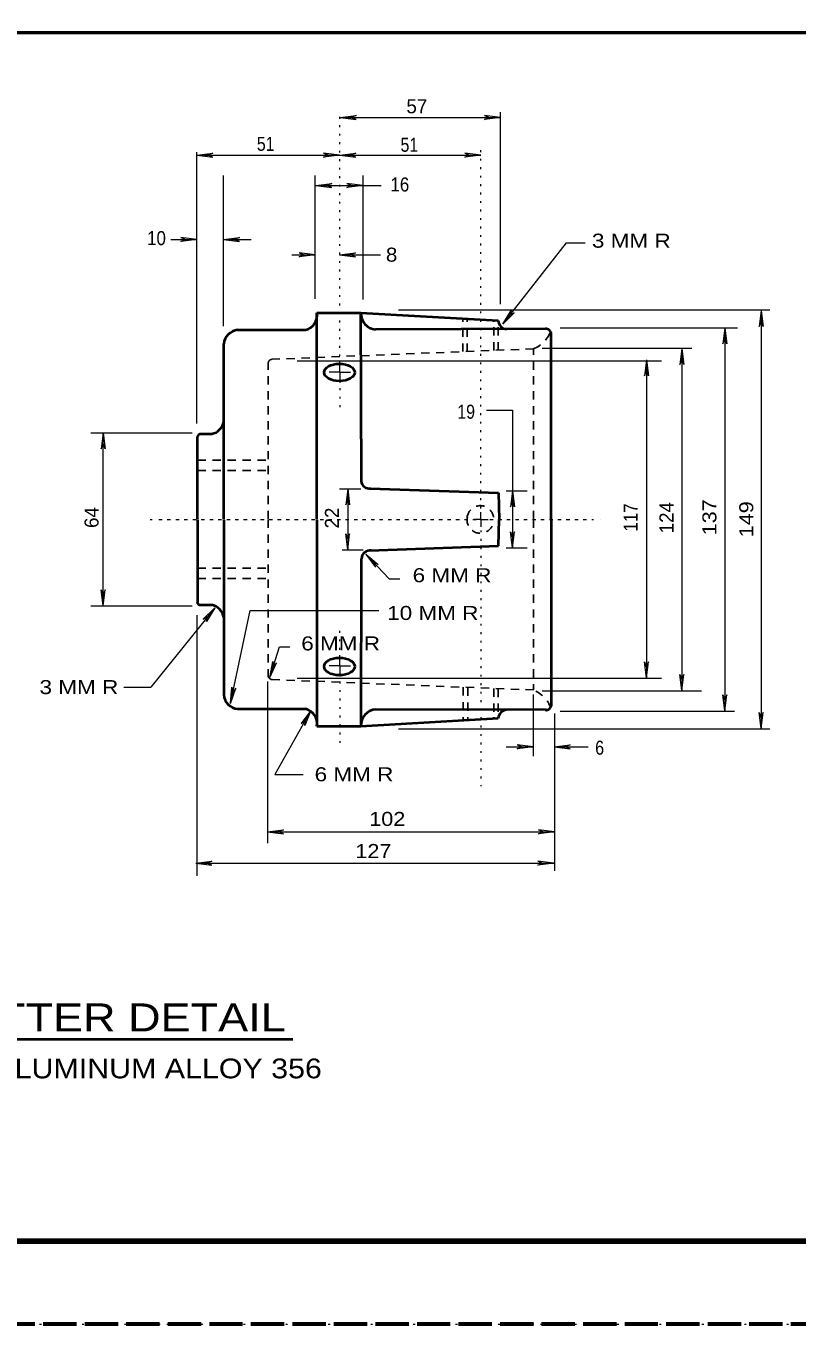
# Model space of a CAD drawing. Extents: x 312583 to 312854, y 144419 to 144597.
# Drawn here: x 312752.3 to 312794, y 144418.6 to 144488.9 of the extents above; entities that cross this region are included whole.
import ezdxf
from ezdxf.enums import TextEntityAlignment as Align

# ---------------------------------------------------------------- set-up
doc = ezdxf.new("R2010")
doc.units = 0
doc.header["$LTSCALE"] = 0.3
for name, pattern in [('DOTTED', [1.5, 0.3, -1.2]), ('LONG_DASHED', [7.5, 6, -1.5]), ('SHORT_DASHED', [2.7, 1.5, -1.2])]:
    doc.linetypes.add(name, pattern=pattern)
for name, color, linetype, lineweight in [('1', 7, 'Continuous', 40), ('2', 7, 'Continuous', 13), ('62', 7, 'DOTTED', 13), ('63', 7, 'LONG_DASHED', 60)]:
    doc.layers.add(name, color=color, linetype=linetype, lineweight=lineweight)

msp = doc.modelspace()

# ---------------------------------------------------------------- linework, layer by layer
at = {"layer": '1', "linetype": 'DOTTED', "lineweight": 13}
for p, q in [((312769.2617, 144471.0383), (312769.2617, 144484.2326)), ((312776.9054, 144462.7889), (312776.9054, 144482.3849)), ((312769.2617, 144469.3056), (312769.2617, 144467.9869)), ((312758.996, 144462.1986), (312783.376, 144462.1986)), ((312759.5404, 144462.1986), (312782.6247, 144462.1986)), ((312776.9054, 144461.6006), (312776.9054, 144447.7316)), ((312769.2617, 144455.1299), (312769.2617, 144456.3949)), ((312769.2617, 144453.4049), (312769.2617, 144449.9473))]:
    msp.add_line(p, q, dxfattribs=at)
at = {"layer": '1'}
for p, q in [((312768.0197, 144473.3919), (312770.4117, 144473.3919)), ((312768.0197, 144462.2139), (312768.0197, 144473.3919)), ((312770.4117, 144473.3919), (312777.8484, 144472.9703)), ((312770.4347, 144464.2686), (312770.4117, 144473.3919)), ((312763.7264, 144472.4719), (312767.3987, 144472.4719)), ((312780.4704, 144472.5256), (312771.2014, 144472.4949)), ((312780.7157, 144462.2139), (312780.7157, 144472.3109)), ((312762.9827, 144462.2139), (312762.9827, 144471.7129)), ((312761.549, 144462.2139), (312761.549, 144466.6759)), ((312761.7254, 144466.8293), (312762.3234, 144466.8293)), ((312770.9024, 144463.8776), (312777.856, 144463.6323)), ((312777.856, 144463.6323), (312777.8944, 144462.1986)), ((312761.549, 144462.1833), (312761.549, 144457.7289)), ((312762.9827, 144462.1833), (312762.9827, 144452.6766)), ((312768.0197, 144462.1833), (312768.0197, 144450.9976)), ((312777.856, 144460.7649), (312777.8944, 144462.1986)), ((312780.7157, 144462.1833), (312780.7157, 144452.0863)), ((312770.8717, 144460.5119), (312777.856, 144460.7649)), ((312770.427, 144460.0519), (312770.4117, 144450.9976)), ((312761.7024, 144457.5603), (312762.3234, 144457.5603)), ((312763.7264, 144451.9253), (312767.3987, 144451.9253)), ((312780.4704, 144451.8716), (312771.2014, 144451.9023)), ((312768.0197, 144450.9976), (312770.4117, 144450.9976)), ((312770.4117, 144450.9976), (312777.8484, 144451.4269))]:
    msp.add_line(p, q, dxfattribs=at)
at = {"layer": '1', "linetype": 'SHORT_DASHED', "lineweight": 25}
for p, q in [((312775.924, 144471.2913), (312775.924, 144473.0469)), ((312776.1617, 144471.2913), (312776.1617, 144473.0469)), ((312777.603, 144471.3526), (312777.603, 144472.9703)), ((312777.8407, 144471.3526), (312777.8407, 144472.9703)), ((312765.574, 144470.8773), (312779.7574, 144471.4446)), ((312779.7574, 144462.2139), (312779.7574, 144471.4446)), ((312765.3824, 144462.2139), (312765.3824, 144470.6933)), ((312761.5644, 144465.4033), (312765.367, 144465.4033)), ((312761.5644, 144464.8436), (312765.39, 144464.8436)), ((312765.3824, 144462.1833), (312765.3824, 144453.7039)), ((312779.7574, 144462.1833), (312779.7574, 144452.9526)), ((312761.5644, 144459.5536), (312765.39, 144459.5536)), ((312761.5644, 144458.9863), (312765.367, 144458.9863)), ((312765.574, 144453.5199), (312779.7574, 144452.9526)), ((312775.947, 144453.1059), (312775.947, 144451.3809)), ((312776.2, 144453.0906), (312776.2, 144451.3809)), ((312777.603, 144453.0293), (312777.603, 144451.4193)), ((312777.8407, 144453.0216), (312777.8407, 144451.4193))]:
    msp.add_line(p, q, dxfattribs=at)
at = {"layer": '1', "lineweight": 13}
for p, q in [((312769.2617, 144470.1719), (312769.2617, 144470.7469)), ((312769.2617, 144470.1719), (312768.6867, 144470.1719)), ((312769.2617, 144470.1719), (312769.8367, 144470.1719)), ((312776.9054, 144462.1986), (312776.522, 144462.1986)), ((312776.9054, 144462.2139), (312776.9054, 144462.5973)), ((312776.9054, 144462.2139), (312776.9054, 144462.1986)), ((312776.9054, 144462.1756), (312776.9054, 144462.1986)), ((312776.9054, 144462.1756), (312776.9054, 144461.7923)), ((312776.9207, 144462.1986), (312777.304, 144462.1986)), ((312769.2617, 144454.2636), (312769.2617, 144454.8463)), ((312769.2617, 144454.2636), (312768.6867, 144454.2636)), ((312769.2617, 144454.2636), (312769.8367, 144454.2636))]:
    msp.add_line(p, q, dxfattribs=at)
at = {"layer": '1', "lineweight": 158}
msp.add_line((312616.5, 144423.0846), (312849, 144423.0846), dxfattribs=at)
at = {"layer": '1'}
for centre, radius, start, end in [((312767.2397, 144473.2424), 0.7904, 281.60134, 10.90887), ((312771.2743, 144473.3516), 0.8635, 177.32021, 265.15512), ((312778.3656, 144473.0241), 0.5242, 186.31764, 264.15393), ((312763.8222, 144471.627), 0.847, 96.75979, 174.69804), ((312780.4455, 144472.2616), 0.2639, 354.05802, 99.6372), ((312762.1418, 144467.6752), 0.8652, 282.11581, 348.18326), ((312761.7236, 144466.6442), 0.1812, 90.66314, 169.92115), ((312770.862, 144464.304), 0.433, 185.20357, 279.9535), ((312770.9, 144460.0432), 0.4659, 81.66883, 177.04453), ((312761.7063, 144457.7194), 0.1613, 176.60264, 279.55227), ((312762.1418, 144456.7143), 0.8652, 11.81674, 77.88419), ((312763.8222, 144452.7625), 0.847, 185.30196, 263.24021), ((312767.2397, 144451.1472), 0.7904, 349.09113, 78.39866), ((312771.2743, 144451.038), 0.8635, 94.84488, 182.67979), ((312780.4455, 144452.1279), 0.2639, 260.3628, 5.94198)]:
    msp.add_arc(centre, radius, start, end, dxfattribs=at)
at = {"layer": '1', "linetype": 'SHORT_DASHED', "lineweight": 25}
for centre, radius, start, end in [((312779.1203, 144473.0014), 1.6842, 292.08363, 339.74237), ((312765.6191, 144470.6363), 0.2414, 93.42967, 184.67744), ((312776.8785, 144462.2254), 0.7188, 7.34899, 192.24831), ((312776.8785, 144462.1641), 0.7188, 167.75169, 352.65101), ((312765.6191, 144453.7532), 0.2414, 175.32256, 266.57033), ((312779.1203, 144451.3881), 1.6842, 20.25763, 67.91637)]:
    msp.add_arc(centre, radius, start, end, dxfattribs=at)
at = {"layer": '1'}
for centre in [(312769.2425, 144470.1643), (312769.2425, 144454.2253)]:
    msp.add_ellipse(centre, major_axis=(0.828, 0), ratio=0.569621, dxfattribs=at)
at = {"layer": '2', "lineweight": 53}
msp.add_line((312708.0873, 144488.5949), (312796.6723, 144488.5949), dxfattribs=at)
at = {"layer": '2'}
for p, q in [((312769.277, 144483.9796), (312770.1434, 144484.0869)), ((312769.277, 144483.9796), (312777.9634, 144483.9796)), ((312769.277, 144483.9796), (312770.1434, 144483.8723)), ((312770.1434, 144484.0869), (312769.8674, 144483.9796)), ((312770.1434, 144483.8723), (312769.8674, 144483.9796)), ((312777.097, 144484.0869), (312777.373, 144483.9796)), ((312777.9634, 144483.9796), (312777.097, 144484.0869)), ((312777.097, 144483.8723), (312777.373, 144483.9796)), ((312777.9634, 144483.9796), (312777.097, 144483.8723)), ((312777.971, 144473.8596), (312777.971, 144484.2709)), ((312761.5184, 144467.3966), (312761.5184, 144482.1089)), ((312761.5184, 144481.9403), (312762.3847, 144482.0476)), ((312761.5184, 144481.9403), (312762.3847, 144481.8329)), ((312761.5184, 144481.9403), (312769.254, 144481.9403)), ((312762.3847, 144482.0476), (312762.1087, 144481.9403)), ((312762.3847, 144481.8329), (312762.1087, 144481.9403)), ((312768.3877, 144482.0476), (312768.6637, 144481.9403)), ((312769.254, 144481.9403), (312768.3877, 144482.0476)), ((312768.3877, 144481.8329), (312768.6637, 144481.9403)), ((312769.254, 144481.9403), (312768.3877, 144481.8329)), ((312769.2617, 144481.9403), (312770.128, 144482.0476)), ((312769.2617, 144481.9403), (312770.128, 144482.0476)), ((312769.2617, 144481.9403), (312776.9054, 144481.9403)), ((312769.2617, 144481.9403), (312770.128, 144481.8329)), ((312769.2617, 144481.9403), (312770.128, 144481.8329)), ((312770.128, 144482.0476), (312769.852, 144481.9403)), ((312770.128, 144482.0476), (312769.852, 144481.9403)), ((312770.128, 144481.8329), (312769.852, 144481.9403)), ((312770.128, 144481.8329), (312769.852, 144481.9403)), ((312776.039, 144482.0476), (312776.315, 144481.9403)), ((312776.9054, 144481.9403), (312776.039, 144482.0476)), ((312776.039, 144481.8329), (312776.315, 144481.9403)), ((312776.9054, 144481.9403), (312776.039, 144481.8329)), ((312762.9674, 144472.6713), (312762.9674, 144480.8363)), ((312767.9354, 144474.1586), (312767.9354, 144480.8363)), ((312767.9584, 144480.2996), (312768.8247, 144480.4069)), ((312767.9584, 144480.2996), (312768.8247, 144480.4069)), ((312768.8247, 144480.4069), (312768.5487, 144480.2996)), ((312768.8247, 144480.4069), (312768.5487, 144480.2996)), ((312769.6527, 144480.4069), (312769.9287, 144480.2996)), ((312770.519, 144480.2996), (312769.6527, 144480.4069)), ((312770.5344, 144474.1126), (312770.5344, 144480.8363)), ((312767.9584, 144480.2996), (312771.5123, 144480.2996)), ((312767.9584, 144480.2996), (312768.8247, 144480.1923)), ((312767.9584, 144480.2996), (312768.8247, 144480.1923)), ((312768.8247, 144480.1923), (312768.5487, 144480.2996)), ((312768.8247, 144480.1923), (312768.5487, 144480.2996)), ((312769.6527, 144480.1923), (312769.9287, 144480.2996)), ((312770.519, 144480.2996), (312769.6527, 144480.1923)), ((312760.1077, 144477.3633), (312761.5107, 144477.3633)), ((312760.6444, 144477.4706), (312760.9204, 144477.3633)), ((312761.5107, 144477.3633), (312760.6444, 144477.4706)), ((312760.6444, 144477.2559), (312760.9204, 144477.3633)), ((312761.5107, 144477.3633), (312760.6444, 144477.2559)), ((312762.9597, 144477.3633), (312763.826, 144477.4706)), ((312762.9597, 144477.3633), (312764.47, 144477.3633)), ((312762.9597, 144477.3633), (312763.826, 144477.2559)), ((312763.826, 144477.4706), (312763.55, 144477.3633)), ((312763.826, 144477.2559), (312763.55, 144477.3633)), ((312778.0937, 144472.7786), (312781.5437, 144477.1869)), ((312781.5437, 144477.1869), (312782.5634, 144477.1869)), ((312766.6627, 144476.5429), (312767.9277, 144476.5429)), ((312767.0614, 144476.6503), (312767.3374, 144476.5429)), ((312767.9277, 144476.5429), (312767.0614, 144476.6503)), ((312767.0614, 144476.4356), (312767.3374, 144476.5429)), ((312767.9277, 144476.5429), (312767.0614, 144476.4356)), ((312769.2464, 144476.5429), (312770.1127, 144476.6503)), ((312769.2464, 144476.5429), (312770.1127, 144476.6503)), ((312769.2464, 144476.5429), (312771.4769, 144476.5429)), ((312769.2464, 144476.5429), (312770.1127, 144476.4356)), ((312769.2464, 144476.5429), (312770.1127, 144476.4356)), ((312770.1127, 144476.6503), (312769.8367, 144476.5429)), ((312770.1127, 144476.6503), (312769.8367, 144476.5429)), ((312770.1127, 144476.4356), (312769.8367, 144476.5429)), ((312770.1127, 144476.4356), (312769.8367, 144476.5429)), ((312772.4434, 144473.5529), (312792.5607, 144473.5529)), ((312778.0937, 144472.7786), (312778.546, 144473.5299)), ((312778.0937, 144472.7786), (312778.7147, 144473.3996)), ((312778.546, 144473.5299), (312778.4617, 144473.2463)), ((312778.7147, 144473.3996), (312778.4617, 144473.2463)), ((312792.093, 144473.5223), (312791.9857, 144472.6559)), ((312792.093, 144473.5223), (312791.9857, 144472.6559)), ((312792.093, 144473.5223), (312792.093, 144450.8596)), ((312792.093, 144473.5223), (312792.2004, 144472.6559)), ((312792.093, 144473.5223), (312792.2004, 144472.6559)), ((312791.9857, 144472.6559), (312792.093, 144472.9319)), ((312791.9857, 144472.6559), (312792.093, 144472.9319)), ((312792.2004, 144472.6559), (312792.093, 144472.9319)), ((312792.2004, 144472.6559), (312792.093, 144472.9319)), ((312781.2064, 144472.5869), (312790.8127, 144472.5869)), ((312790.1304, 144472.5869), (312790.023, 144471.7206)), ((312790.023, 144471.7206), (312790.1304, 144471.9966)), ((312790.1304, 144472.5869), (312790.2377, 144471.7206)), ((312790.1304, 144472.5869), (312790.1304, 144451.8179)), ((312790.2377, 144471.7206), (312790.1304, 144471.9966)), ((312780.225, 144471.4753), (312788.3287, 144471.4753)), ((312787.792, 144471.4599), (312787.6847, 144470.5936)), ((312787.7767, 144471.4753), (312788.344, 144471.4753)), ((312787.792, 144471.4599), (312787.8994, 144470.5936)), ((312787.792, 144471.4599), (312787.792, 144452.9219)), ((312766.9617, 144470.8006), (312786.688, 144470.8006)), ((312785.8754, 144470.8389), (312785.768, 144469.9726)), ((312785.8754, 144470.8389), (312785.9827, 144469.9726)), ((312785.8754, 144470.8389), (312785.8754, 144453.6043)), ((312787.6847, 144470.5936), (312787.792, 144470.8696)), ((312787.8994, 144470.5936), (312787.792, 144470.8696)), ((312769.2617, 144470.1719), (312769.2617, 144469.5969)), ((312785.768, 144469.9726), (312785.8754, 144470.2486)), ((312785.9827, 144469.9726), (312785.8754, 144470.2486)), ((312777.212, 144468.1173), (312778.615, 144468.1173)), ((312778.615, 144468.1173), (312778.615, 144460.6499)), ((312755.776, 144466.8829), (312761.2654, 144466.8829)), ((312756.4507, 144466.8983), (312756.3434, 144466.0319)), ((312756.4507, 144457.5066), (312756.4507, 144466.8983)), ((312756.4507, 144466.8983), (312756.558, 144466.0319)), ((312756.3434, 144466.0319), (312756.4507, 144466.3079)), ((312756.558, 144466.0319), (312756.4507, 144466.3079)), ((312769.254, 144463.8623), (312770.404, 144463.8623)), ((312769.691, 144463.8469), (312769.5837, 144462.9806)), ((312769.691, 144463.8623), (312769.691, 144460.5426)), ((312769.691, 144463.8469), (312769.7984, 144462.9806)), ((312778.27, 144463.7396), (312779.42, 144463.7396)), ((312778.615, 144463.7396), (312778.5077, 144462.8733)), ((312778.615, 144463.7396), (312778.7224, 144462.8733)), ((312769.5837, 144462.9806), (312769.691, 144463.2566)), ((312769.7984, 144462.9806), (312769.691, 144463.2566)), ((312778.5077, 144462.8733), (312778.615, 144463.1493)), ((312778.7224, 144462.8733), (312778.615, 144463.1493)), ((312769.5837, 144461.4089), (312769.691, 144461.1329)), ((312769.691, 144460.5426), (312769.5837, 144461.4089)), ((312769.7984, 144461.4089), (312769.691, 144461.1329)), ((312769.691, 144460.5426), (312769.7984, 144461.4089)), ((312778.5077, 144461.5163), (312778.615, 144461.2403)), ((312778.615, 144460.6499), (312778.5077, 144461.5163)), ((312778.7224, 144461.5163), (312778.615, 144461.2403)), ((312778.615, 144460.6499), (312778.7224, 144461.5163)), ((312769.3844, 144460.5426), (312770.5344, 144460.5426)), ((312771.945, 144458.9786), (312770.6724, 144460.3126)), ((312770.6724, 144460.3126), (312771.1937, 144459.6149)), ((312770.6724, 144460.3126), (312771.347, 144459.7606)), ((312778.27, 144460.6576), (312779.42, 144460.6576)), ((312771.1937, 144459.6149), (312771.0787, 144459.8909)), ((312771.347, 144459.7606), (312771.0787, 144459.8909)), ((312771.945, 144458.9786), (312772.5124, 144458.9786)), ((312756.3434, 144458.3729), (312756.4507, 144458.0969)), ((312756.4507, 144457.5066), (312756.3434, 144458.3729)), ((312756.558, 144458.3729), (312756.4507, 144458.0969)), ((312756.4507, 144457.5066), (312756.558, 144458.3729)), ((312755.776, 144457.5066), (312761.2654, 144457.5066)), ((312762.4997, 144457.3993), (312759.019, 144453.0983)), ((312762.4997, 144457.3993), (312761.871, 144456.7936)), ((312762.4997, 144457.3993), (312762.0397, 144456.6633)), ((312761.5184, 144457.0006), (312761.5184, 144442.8786)), ((312761.871, 144456.7936), (312762.124, 144456.9393)), ((312762.0397, 144456.6633), (312762.124, 144456.9393)), ((312765.482, 144453.6349), (312765.9957, 144455.2909)), ((312765.9957, 144455.2909), (312766.5631, 144455.2909)), ((312765.482, 144453.6349), (312765.6354, 144454.4936)), ((312765.482, 144453.6349), (312765.8424, 144454.4323)), ((312765.6354, 144454.4936), (312765.6584, 144454.1946)), ((312765.8424, 144454.4323), (312765.6584, 144454.1946)), ((312785.768, 144454.4706), (312785.8754, 144454.1946)), ((312785.8754, 144453.6043), (312785.768, 144454.4706)), ((312785.9827, 144454.4706), (312785.8754, 144454.1946)), ((312785.8754, 144453.6043), (312785.9827, 144454.4706)), ((312769.2617, 144454.2636), (312769.2617, 144453.6886)), ((312787.6847, 144453.7883), (312787.792, 144453.5123)), ((312787.792, 144452.9219), (312787.6847, 144453.7883)), ((312787.8994, 144453.7883), (312787.792, 144453.5123)), ((312787.792, 144452.9219), (312787.8994, 144453.7883)), ((312757.5624, 144453.0983), (312759.019, 144453.0983)), ((312763.3507, 144452.2243), (312763.4197, 144453.0983)), ((312763.3507, 144452.2243), (312763.6344, 144453.0523)), ((312763.4197, 144453.0983), (312763.4734, 144452.8069)), ((312763.6344, 144453.0523), (312763.4734, 144452.8069)), ((312765.3517, 144453.4203), (312765.3517, 144444.6419)), ((312766.9617, 144453.5966), (312786.688, 144453.5966)), ((312779.742, 144452.6996), (312779.742, 144449.8553)), ((312780.225, 144452.9143), (312788.85, 144452.9143)), ((312790.023, 144452.6843), (312790.1304, 144452.4083)), ((312790.1304, 144451.8179), (312790.023, 144452.6843)), ((312790.2377, 144452.6843), (312790.1304, 144452.4083)), ((312790.1304, 144451.8179), (312790.2377, 144452.6843)), ((312767.6977, 144451.8409), (312767.1764, 144451.1433)), ((312767.6977, 144451.8409), (312767.368, 144451.0359)), ((312780.892, 144451.6723), (312780.892, 144443.1469)), ((312781.2064, 144451.8103), (312790.644, 144451.8103)), ((312791.9857, 144451.7259), (312792.093, 144451.4499)), ((312792.093, 144450.8596), (312791.9857, 144451.7259)), ((312792.2004, 144451.7259), (312792.093, 144451.4499)), ((312792.093, 144450.8596), (312792.2004, 144451.7259)), ((312767.1764, 144451.1433), (312767.4064, 144451.3273)), ((312767.368, 144451.0359), (312767.4064, 144451.3273)), ((312772.4434, 144450.8443), (312792.5607, 144450.8443)), ((312778.2696, 144449.8629), (312779.7344, 144449.8629)), ((312778.868, 144449.9703), (312779.144, 144449.8629)), ((312779.7344, 144449.8629), (312778.868, 144449.9703)), ((312778.868, 144449.7556), (312779.144, 144449.8629)), ((312779.7344, 144449.8629), (312778.868, 144449.7556)), ((312779.742, 144449.8399), (312779.742, 144449.3646)), ((312780.8767, 144449.8629), (312781.743, 144449.9703)), ((312780.8767, 144449.8629), (312782.7166, 144449.8629)), ((312780.8767, 144449.8629), (312781.743, 144449.7556)), ((312781.743, 144449.9703), (312781.467, 144449.8629)), ((312781.743, 144449.7556), (312781.467, 144449.8629)), ((312765.3517, 144445.2629), (312766.218, 144445.3703)), ((312765.3517, 144445.2629), (312780.892, 144445.2629)), ((312765.3517, 144445.2629), (312766.218, 144445.1556)), ((312766.218, 144445.3703), (312765.942, 144445.2629)), ((312766.218, 144445.1556), (312765.942, 144445.2629)), ((312780.0257, 144445.3703), (312780.3017, 144445.2629)), ((312780.892, 144445.2629), (312780.0257, 144445.3703)), ((312780.0257, 144445.1556), (312780.3017, 144445.2629)), ((312780.892, 144445.2629), (312780.0257, 144445.1556)), ((312761.4724, 144443.5609), (312762.3387, 144443.6683)), ((312761.4724, 144443.5609), (312780.8537, 144443.5609)), ((312761.4724, 144443.5609), (312762.3387, 144443.4536)), ((312762.3387, 144443.6683), (312762.0627, 144443.5609)), ((312762.3387, 144443.4536), (312762.0627, 144443.5609)), ((312779.9874, 144443.6683), (312780.2634, 144443.5609)), ((312780.8537, 144443.5609), (312779.9874, 144443.6683)), ((312779.9874, 144443.4536), (312780.2634, 144443.5609)), ((312780.8537, 144443.5609), (312779.9874, 144443.4536))]:
    msp.add_line(p, q, dxfattribs=at)
at = {"layer": '2', "lineweight": 25}
for p, q in [((312775.924, 144472.9319), (312775.924, 144473.0776)), ((312776.1617, 144472.9473), (312776.1617, 144473.0623)), ((312777.603, 144472.9013), (312777.603, 144472.9856)), ((312777.8407, 144472.8783), (312777.8484, 144472.9703)), ((312775.947, 144451.4116), (312775.947, 144451.3196)), ((312776.2, 144451.4193), (312776.2, 144451.3273)), ((312777.603, 144451.4806), (312777.603, 144451.4116)), ((312777.8407, 144451.4806), (312777.8407, 144451.4269))]:
    msp.add_line(p, q, dxfattribs=at)
at = {"layer": '2', "lineweight": 40}
msp.add_line((312742.5584, 144434.032), (312766.7242, 144434.032), dxfattribs=at)
at = {"layer": '2'}
for points in [[(312763.3507, 144452.2243), (312764.401, 144457.2689), (312771.37, 144457.2689)], [(312767.6977, 144451.8409), (312765.7427, 144448.3679), (312767.2837, 144448.3679)]]:
    msp.add_lwpolyline(points, dxfattribs=at)
at = {"layer": '2', "lineweight": 40}
msp.add_arc((312778.3568, 144451.3661), 0.5154, 98.8259, 173.65405, dxfattribs=at)
at = {"layer": '62'}
msp.add_lwpolyline([(312601.2, 144418.5846), (312853.5, 144418.5846), (312853.5, 144596.7846)], dxfattribs=at)
at = {"layer": '63'}
msp.add_line((312851.75, 144418.5846), (312583.526, 144418.5846), dxfattribs=at)

# ---------------------------------------------------------------- texts
at = {"layer": '2'}
msp.add_text('57', height=0.76, dxfattribs=at).set_placement((312772.873, 144484.2124))
for s, width, p in [('51', 0.85, (312764.7698, 144482.1741)), ('51', 0.85, (312772.5537, 144482.1252)), ('16', 0.9, (312772.0095, 144479.9728)), ('10', 0.9, (312758.8257, 144477.0653)), ('3 MM R', 1.2, (312782.9218, 144476.9252)), ('8 ', 1.1, (312771.761, 144476.1673)), ('19', 0.85, (312775.629, 144467.6554)), ('6 MM R', 1.2, (312773.21, 144458.7936)), ('10 MM R', 1.2, (312771.83, 144456.7466)), ('6 MM R', 1.2, (312767.1759, 144455.0973)), ('3 MM R', 1.2, (312752.9974, 144452.7284)), ('6', 0.85, (312783.0997, 144449.4451)), ('6 MM R', 1.2, (312767.9001, 144448.0028)), ('102 ', 1.15, (312770.861, 144445.584)), ('127 ', 1.15, (312770.1094, 144443.8437))]:
    msp.add_text(s, height=0.76, dxfattribs=dict(at, width=width)).set_placement(p)
for s, p in [('64', (312756.1952, 144461.7324)), ('124', (312787.3421, 144461.4434)), ('22', (312769.2177, 144461.7076))]:
    msp.add_text(s, height=0.76, rotation=90, dxfattribs=at).set_placement(p)
for s, width, p in [('117', 0.9, (312785.4014, 144461.5433)), ('137 ', 1.15, (312789.667, 144461.337)), ('149 ', 1.15, (312791.665, 144461.2307))]:
    msp.add_text(s, height=0.76, rotation=90, dxfattribs=dict(at, width=width)).set_placement(p)
for s, height, width, p in [('SLIP FITTER DETAIL', 1.52, 1.2, (312754.4751, 144434.4435)), ('MATERIAL: ALUMINUM ALLOY 356', 1.07, 1.15, (312754.85, 144431.9034))]:
    msp.add_text(s, height=height, dxfattribs=dict(at, width=width)).set_placement(p, align=Align.CENTER)

doc.saveas('drawing.dxf')
